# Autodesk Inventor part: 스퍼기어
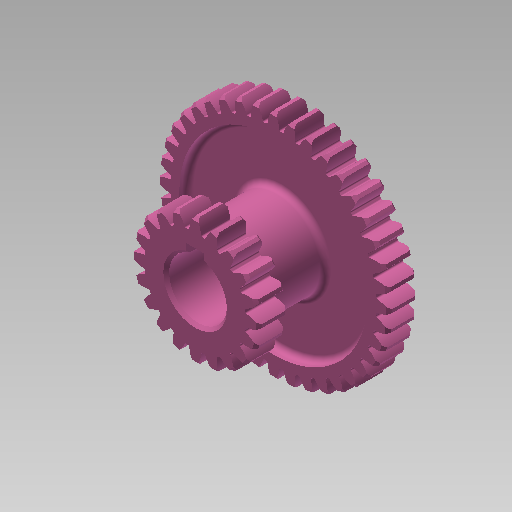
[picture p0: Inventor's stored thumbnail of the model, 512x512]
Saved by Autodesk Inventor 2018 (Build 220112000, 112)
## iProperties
Created: 2015-09
Part Number: 스퍼기어
Material: 강철, 연강
Document SubType Name: Modeling
Designer: mduedu
Density: 7.86 g/cm^3
Mass: 345.726 g
Surface Area: 225.641 cm^2
Volume: 43.9855 cm^3
Appearance: 분홍색
Author: mduedu
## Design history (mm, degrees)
sketch "스케치1"
  geometry: C1 r 38 at (0, 0); C2 r 40 at (0, 0); C3 r 35.5 at (0, 0); 1 further point
  constraints: 3 centre point, 3 coincident
  dimensions: "d0" = 76 diameter of C1; "d2" = 2 radial gap between concentric circles of C2 C1; "d3" = 71 diameter of C3 (computed from d0)
extrude "돌출1" new body sketch "스케치1" stored distance "d4" = 10; taper "d5" = 0 deg
sketch "스케치2"
  geometry: L1 (0, 35.5)-(0, -35.5); L2 (0, 0)-(40, 0); L3 (0, 0.57)-(39.996, 0.57); L4 (0, 1.57)-(39.969, 1.57); L5 (0, 2.07)-(39.946, 2.07); A1 r 35.5 centre (0, 0) between (0, 35.5) and (0, -35.5) reference; A2 r 40 centre (0, 0) between (40, 0) and (39.946, 2.07) reference; A3 r 9.234 centre (34.93, -7.149) between (39.996, 0.57) and (35.44, 2.07); A4 r 9.234 centre (34.93, 7.149) between (35.44, -2.07) and (39.996, -0.57); A5 r 40 centre (0, 0) between (39.996, -0.57) and (39.996, 0.57); A6 r 35.5 centre (0, 0) between (35.44, -2.07) and (35.44, 2.07); 4 further points
  constraints: 16 point on circle, 10 end point, 6 point on line, 4 centre point, 3 coincident, 3 parallel, 3 symmetric about line, 2 midpoint, 1 perpendicular, 1 vertical, 3 other
  dimensions: "d6" = 0.5 distance between parallel lines of L4 L5; "d8" = 1 distance between parallel lines of L3 L4; "d9" = 1.57 distance between parallel lines of L2 L4
extrude "돌출2" join sketch "스케치2" distance "d10" = 5; taper "d12" = 0 deg; dims "d11" = 5, "d13" = 0
fillet "모깎기1" dims "d17" = 0.5
chamfer "모따기1" distance "d21" = 1; stored, may be unused: second distance "d22" = 2, angle "d23" = 45 deg
sketch "스케치3"
  geometry: C1 r 32.5 at (0, 0); C2 r 15 at (0, 0); 1 further point
  constraints: 2 centre point, 2 coincident
  dimensions: "d27" = 65 diameter of C1; "d28" = 30 diameter of C2
extrude "돌출3" cut sketch "스케치3" distance "d29" = 3; taper "d30" = 0 deg
fillet "모깎기2" dims "d31" = 2
node "작업 평면2"
  node "작업 평면1"
sketch "스케치4"
  geometry: C1 r 15 at (0, 0) reference; 1 further point
extrude "돌출4" join sketch "스케치4" stored distance "d34" = 3; taper "d35" = 0 deg
sketch "스케치5"
  geometry: C1 r 17.5 at (0, 0); C2 r 20 at (0, 0); C3 r 22 at (0, 0); 1 further point
  constraints: 3 centre point, 3 coincident
  dimensions: "d36" = 40 diameter of C2; "d38" = 2 radial gap between concentric circles of C2 C3; "d39" = 35 diameter of C1 (= d36 - 2.5 x d38)
extrude "돌출6" join sketch "스케치5" distance "d46" = 10; taper "d47" = 0 deg
sketch "스케치6"
  geometry: L1 (0, 0)-(0, 22); L2 (-17.5, 0)-(17.5, 0); L3 (-0.57, 0)-(-0.57, 21.993); L4 (-1.57, 0)-(-1.57, 21.944); L5 (-2.07, 0)-(-2.07, 21.902); A1 r 22 centre (0, 0) between (0, 22) and (-0.57, 21.993) reference; A2 r 17.5 centre (0, 0) between (-17.5, 0) and (17.5, 0) reference; A3 r 9.431 centre (7.348, 16.868) between (-0.57, 21.993) and (-2.07, 17.377); A4 r 9.431 centre (-7.348, 16.868) between (2.07, 17.377) and (0.57, 21.993); A5 r 17.5 centre (0, 0) between (2.07, 17.377) and (-2.07, 17.377); A6 r 22 centre (0, 0) between (0.57, 21.993) and (-0.57, 21.993); 4 further points
  constraints: 16 point on circle, 10 end point, 5 point on line, 4 centre point, 3 coincident, 3 symmetric about line, 2 parallel, 2 perpendicular, 1 midpoint, 1 vertical, 3 other
  dimensions: "d40" = 0.5 distance between parallel lines of L4 L5; "d42" = 1 distance between parallel lines of L3 L4; "d43" = 1.57 distance between parallel lines of L1 L4
extrude "돌출5" join sketch "스케치6" distance "d44" = 10; taper "d45" = 0 deg
fillet "모깎기3" dims "d48" = 0.5
chamfer "모따기2" distance "d49" = 1; stored, may be unused: second distance "d50" = 2, angle "d51" = 45 deg
sketch "스케치7"
  geometry: C1 r 10 at (0, 0); 1 further point
  constraints: 1 centre point, 1 coincident
  dimensions: "d55" = 20 diameter of C1
extrude "돌출7" cut sketch "스케치7" extent not by distance; stored distance "d56" = 10; taper "d57" = 0 deg
sketch "스케치8"
  geometry: L1 (-9.539, -3)-(-12.8, -3); L2 (-12.8, -3)-(-12.8, 3); L3 (-12.8, 3)-(-9.539, 3); L4 (-9.539, 3)-(-9.539, -3); A1 r 10 centre (0, 0) between (-9.539, -3) and (-9.539, 3) reference; 2 further points
  constraints: 8 end point, 3 point on circle, 2 parallel, 1 horizontal, 1 horizontal alignment, 1 perpendicular
  dimensions: "d58" = 6 distance of L1.end L2.end; "d60" = 22.8 distance from line of point (10, 0) L2
extrude "돌출8" cut sketch "스케치8" extent not by distance; stored distance "d61" = 10; taper "d62" = 0 deg
chamfer "모따기3" distance "d63" = 1; stored, may be unused: second distance "d64" = 2, angle "d65" = 45 deg
fillet "모깎기4" dims "d66" = 2
node "솔리드1"
pattern_circular "원형 패턴3" dims angle "d25" = 360 deg
mirror "대칭1"
pattern_circular "원형 패턴4" dims angle "d53" = 360 deg
other parameters: "d32" = 5, "d33" = 42
